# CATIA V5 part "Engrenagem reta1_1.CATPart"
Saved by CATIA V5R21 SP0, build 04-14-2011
Part number: Engrenagem reta1_1
Definition: Engrenagem reta1_1
Nomenclature: Engrenagem reta11
Source: Unknown
Bounding box of the stored display mesh (mm): x -0.954 to 0.954, y -0.958 to 0.958, z 0 to 1.5
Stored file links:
  C:\Users\beatr\OneDrive\Documents\UNB\2026_1\Pi1\Componentes eletronicos\Engrenagem reta1_1.CATPart
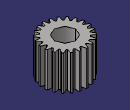
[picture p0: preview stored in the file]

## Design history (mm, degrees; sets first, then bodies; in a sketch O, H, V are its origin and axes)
Body1 "Solid1" (main body)
  Solid1: solid without history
